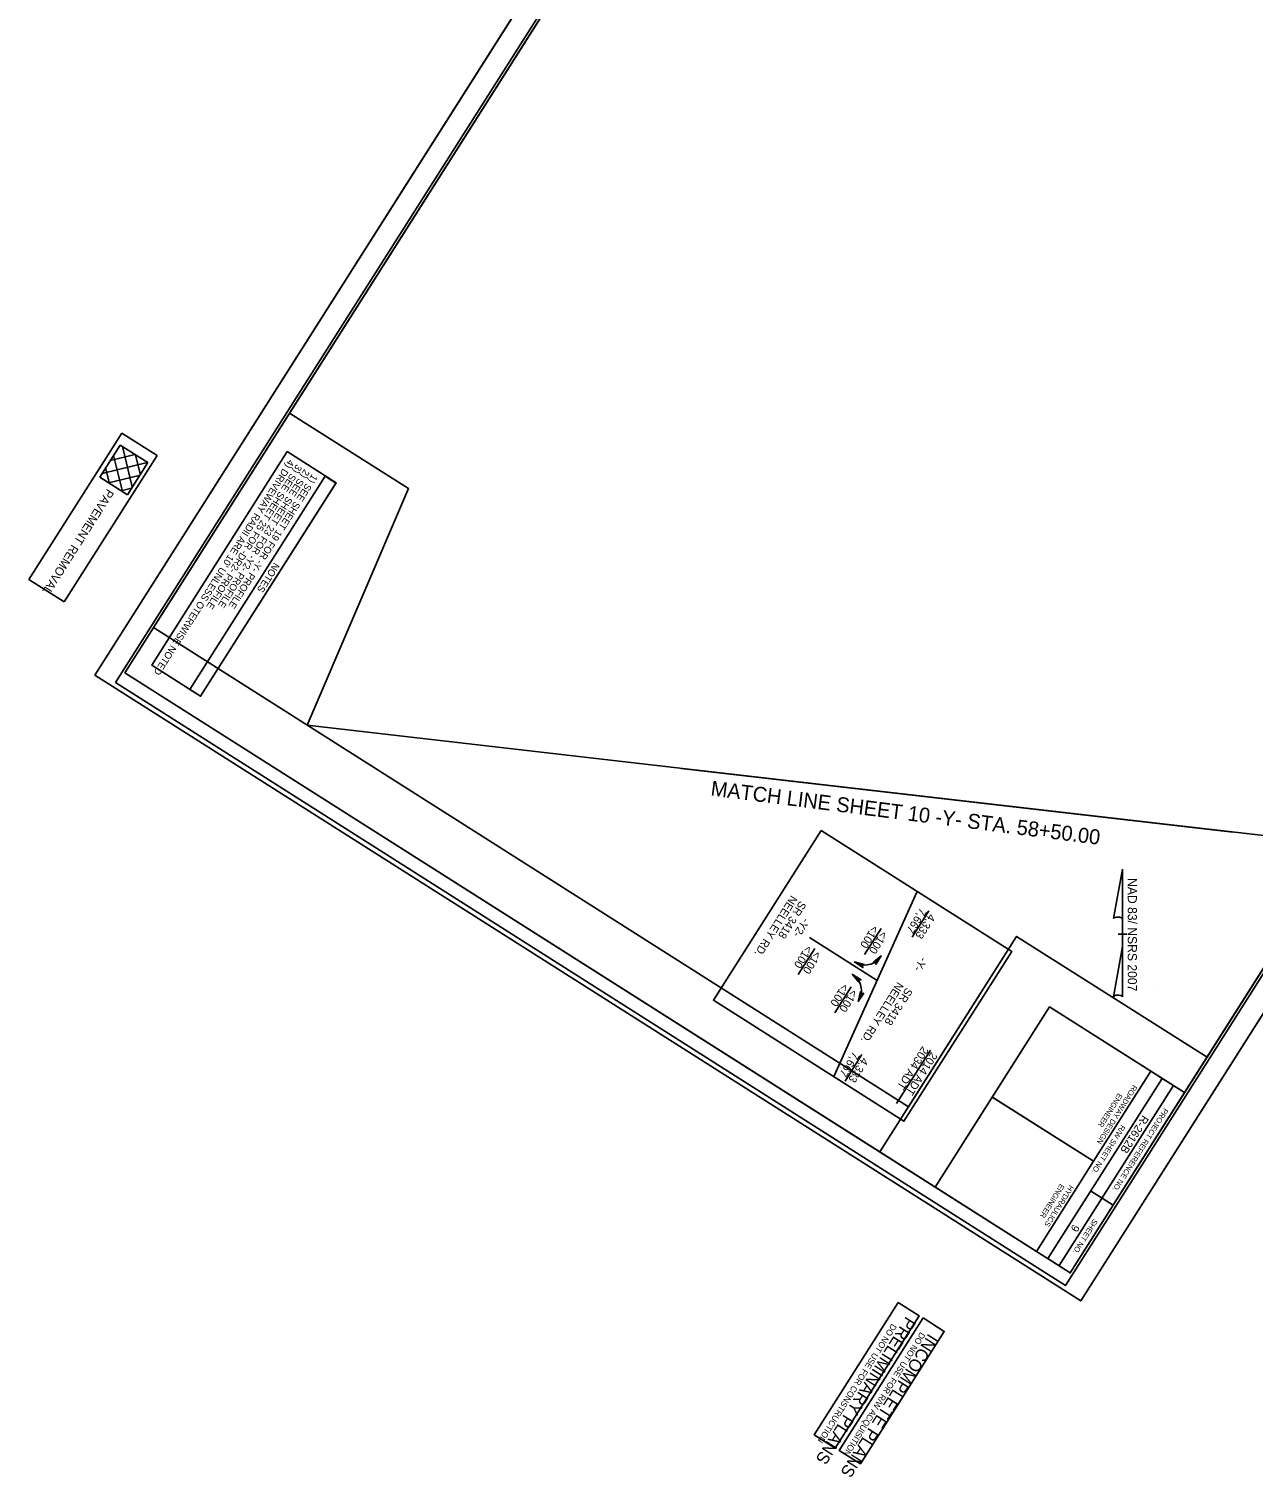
# Model space of a CAD drawing. Extents: x 1780138 to 1782093, y 811157 to 813450.
# Drawn here: x 1780138 to 1781286, y 811157 to 812514 of the extents above; entities that cross this region are included whole.
import ezdxf

# ---------------------------------------------------------------- set-up
doc = ezdxf.new("R2010")
doc.units = 0
for name, color, linetype in [('Prop Easement Aerial Utility', 7, 'Continuous'), ('Prop Easement Construction Station Offsets', 7, 'Continuous'), ('Prop Easement Danger Tree Area', 7, 'Continuous'), ('Prop Easement Danger Tree Area Text', 7, 'Continuous'), ('Prop Easement Permanent Drainage', 7, 'Continuous'), ('Prop Easement Permanent Drainage Station Offsets', 7, 'Continuous'), ('Prop Easement Permanent Drainage Utility', 7, 'Continuous'), ('Prop Easement Permanent Drainage Utility Station Offsets', 7, 'Continuous'), ('Prop Easement Permanent Utility', 7, 'Continuous'), ('Prop Easement Permanent Utility Station Offsets', 7, 'Continuous'), ('Prop Easement Temporary Drainage', 7, 'Continuous'), ('Prop Easement Temporary Drainage Station Offsets', 7, 'Continuous'), ('Prop Easement Temporary Utility', 7, 'Continuous'), ('Prop Easement Temporary Utility Station Offsets', 7, 'Continuous'), ('Prop Parcel Number CELL', 7, 'Continuous'), ('Prop ROW CA Lines', 7, 'Continuous'), ('Prop ROW Marker CELL', 7, 'Continuous'), ('Prop ROW Station Offsets', 7, 'Continuous')]:
    doc.layers.add(name, color=color, linetype=linetype)

msp = doc.modelspace()

# ---------------------------------------------------------------- linework, layer by layer
at = {"layer": 'Prop Easement Aerial Utility'}
for p, q in [((1781101.7, 813330), (1780199.6, 811908.6)), ((1781124.1, 811321.9), (1782026.2, 812743.3))]:
    msp.add_line(p, q, dxfattribs=at)
at = {"layer": 'Prop Easement Danger Tree Area'}
msp.add_lwpolyline([(1780976.3, 811306), (1780996.1, 811293.4), (1780917.4, 811169.3), (1780897.5, 811181.8)], close=True, dxfattribs=at)
at = {"layer": 'Prop Easement Danger Tree Area Text'}
for p, q in [((1780204.1, 812094.1), (1780223.2, 812124.2)), ((1780237, 812115.5), (1780214.1, 812109.9)), ((1780223.2, 812124.2), (1780249.1, 812107.8)), ((1780225.3, 812122.9), (1780234.6, 812085.1)), ((1780237.5, 812115.2), (1780241.9, 812097.2)), ((1780248.4, 812108), (1780206.3, 812097.7)), ((1780209.6, 812102.8), (1780213.2, 812088.4)), ((1780217, 812114.5), (1780225.4, 812080.6)), ((1780249.1, 812107.8), (1780230, 812077.7)), ((1780230, 812077.7), (1780204.1, 812094.1)), ((1780241.1, 812095.9), (1780212.4, 812088.9)), ((1780233.9, 812083.8), (1780224.1, 812081.4))]:
    msp.add_line(p, q, dxfattribs=at)
at = {"layer": 'Prop Easement Permanent Drainage'}
msp.add_lwpolyline([(1780952.8, 811320.5), (1780972.6, 811307.9), (1780893.9, 811183.8), (1780874, 811196.4)], close=True, dxfattribs=at)
at = {"layer": 'Prop Easement Permanent Drainage Utility'}
msp.add_line((1781196.3, 811613.7), (1781196.3, 811613.7), dxfattribs=at)
at = {"layer": 'Prop Easement Permanent Drainage Utility Station Offsets'}
for p, q in [((1780224.8, 812135.5), (1780137.7, 811998.3)), ((1780258, 812114.5), (1780224.8, 812135.5)), ((1780170.8, 811977.2), (1780258, 812114.5)), ((1780137.7, 811998.3), (1780170.8, 811977.2))]:
    msp.add_line(p, q, dxfattribs=at)
for points in [[(1780379.8, 812118.1), (1780252.8, 811918), (1780298.7, 811888.8), (1780425.7, 812088.9)], [(1780415.5, 812095.1), (1780288.6, 811895.2), (1780298.7, 811888.8), (1780425.6, 812088.7)]]:
    msp.add_lwpolyline(points, close=True, dxfattribs=at)
at = {"layer": 'Prop Easement Permanent Utility'}
msp.add_lwpolyline([(1781004.7, 813135.2), (1780254.5, 811953.1), (1780962.5, 811503.8), (1781063.9, 811663.6), (1781242.5, 811550.3), (1781891.2, 812572.6)], close=True, dxfattribs=at)
at = {"layer": 'Prop Easement Permanent Utility Station Offsets'}
for p, q in [((1780892.7, 811533), (1780970.5, 811705.1)), ((1780981.6, 811687.5), (1780965.9, 811662.9)), ((1780936.9, 811671.1), (1780921.3, 811646.6)), ((1780869.6, 811662.6), (1780933.1, 811622.4)), ((1780874.8, 811652.4), (1780859.2, 811627.9)), ((1780908.9, 811616.5), (1780893.3, 811592)), ((1780918.8, 811552.8), (1780903.1, 811528.1)), ((1780983.1, 811556.9), (1780951.4, 811506.9))]:
    msp.add_line(p, q, dxfattribs=at)
for points in [[(1780880.7, 811763), (1781059.4, 811649.6), (1780958.3, 811490.4), (1780779.6, 811603.8)], [(1780921, 811637.4), (1780911.9, 811639.7), (1780919.8, 811634.5), (1780919.4, 811636.5)], [(1780932, 811637.3), (1780937, 811645.3), (1780929.6, 811639.4), (1780931.7, 811639.2)], [(1780915.9, 811620.7), (1780909.9, 811628), (1780918, 811623.1), (1780916, 811622.6)], [(1780920.5, 811610.6), (1780915.4, 811602.7), (1780917.6, 811611.9), (1780918.7, 811610.1)]]:
    msp.add_lwpolyline(points, close=True, dxfattribs=at)
for centre, start, end in [((1780921.6, 811655), 237.6535, 282.0054), ((1780921.6, 811655), 282.0054, 326.3572), ((1780900.2, 811612.6), 13.2994, 57.6513), ((1780900.2, 811612.6), 328.9475, 13.2994)]:
    msp.add_arc(centre, 18.2, start, end, dxfattribs=at)
at = {"layer": 'Prop Easement Temporary Drainage'}
for p, q in [((1781200.3, 811530.6), (1781189.7, 811537.3)), ((1781200.3, 811530.6), (1781093.1, 811361.7)), ((1781200.3, 811530.6), (1781093.1, 811361.7)), ((1781210.9, 811523.9), (1781103.7, 811355)), ((1781136.1, 811452.8), (1781041.2, 811513.1)), ((1781154.4, 811411.7), (1781133.3, 811425))]:
    msp.add_line(p, q, dxfattribs=at)
for points in [[(1781114.3, 811348.3), (1781918, 812614.8), (1781031.5, 813177.4), (1780227.7, 811910.9)], [(1781031.5, 813177.4), (1781918, 812614.8), (1781221.5, 811517.2), (1781094.8, 811597.6), (1780987.6, 811428.7), (1780227.7, 811910.9)], [(1781189.7, 811537.3), (1781136.1, 811452.8), (1781041.1, 811513.1), (1781094.8, 811597.6)], [(1781221.5, 811517.2), (1781114.3, 811348.3), (1781093.1, 811361.7), (1781200.3, 811530.6)], [(1781136.1, 811452.8), (1781082.6, 811368.4), (1780987.6, 811428.7), (1781041.1, 811513.1)]]:
    msp.add_lwpolyline(points, close=True, dxfattribs=at)
at = {"layer": 'Prop Easement Temporary Drainage Station Offsets'}
for p, q in [((1781154.9, 811680.4), (1781163.1, 811726.7)), ((1781163.1, 811726.7), (1781163.1, 811726.7)), ((1781163.1, 811726.7), (1781163.1, 811726.7)), ((1781163.1, 811726.7), (1781163.1, 811678.9)), ((1781163.1, 811654.1), (1781163.1, 811680.3)), ((1781163.1, 811678.9), (1781163.1, 811680.3)), ((1781163.1, 811654.1), (1781154.8, 811606.9)), ((1781162.7, 811665.7), (1781159.1, 811665.7)), ((1781159.1, 811665.7), (1781159.1, 811665.7)), ((1781159.2, 811665.7), (1781167.2, 811665.7)), ((1781163.2, 811607.1), (1781163.1, 811654.1))]:
    msp.add_line(p, q, dxfattribs=at)
for centre, start_param, end_param in [((1781159, 811679.9), 0.216388, 2.908219), ((1781159, 811606.7), 0.201328, 3.141593)]:
    msp.add_ellipse(centre, major_axis=(4.23, -0.03), ratio=0.461098, start_param=start_param, end_param=end_param, dxfattribs=at)
at = {"layer": 'Prop Easement Temporary Utility'}
for points in [[(1781918, 812614.8), (1781031.5, 813177.4), (1780227.7, 811910.9), (1780935.7, 811461.6), (1781063.9, 811663.6), (1781242.5, 811550.3)], [(1781063.9, 811663.6), (1780935.7, 811461.6), (1781114.2, 811348.2), (1781242.5, 811550.3)]]:
    msp.add_lwpolyline(points, close=True, dxfattribs=at)
at = {"layer": 'Prop Easement Temporary Utility Station Offsets'}
msp.add_line((1780749.2, 811821.2), (1781266.8, 811761.5), dxfattribs=at)
at = {"layer": 'Prop ROW CA Lines'}
msp.add_lwpolyline([(1781101.7, 813330), (1780199.6, 811908.6), (1781124.1, 811321.9), (1782026.2, 812743.3)], close=True, dxfattribs=at)
at = {"layer": 'Prop ROW Marker CELL'}
msp.add_lwpolyline([(1781516.2, 811981.6), (1781369.5, 812074.6), (1781637.4, 812498.2), (1781665.8, 812542.9), (1781507.5, 812669.1), (1780938.2, 813030.4), (1780382.1, 812154.2), (1780493.5, 812083.5), (1780398.6, 811861.6), (1781369, 811749.7)], close=True, dxfattribs=at)
at = {"layer": 'Prop ROW Station Offsets'}
msp.add_lwpolyline([(1781111.6, 813308.3), (1780218.9, 811901.7), (1781109.7, 811336.4), (1782002.3, 812743)], close=True, dxfattribs=at)

# ---------------------------------------------------------------- texts
at = {"layer": 'Prop Easement Construction Station Offsets'}
msp.add_text('MATCH LINE SHEET 10 -Y- STA. 58+50.00', height=14, rotation=352.7698, dxfattribs=at).set_placement((1780776.5, 811795.8))
at = {"layer": 'Prop Easement Danger Tree Area'}
for s, height, p in [('INCOMPLETE PLANS', 11.52, (1780981.4, 811292.1)), ('DO NOT USE FOR R/W ACQUISITION', 5.76, (1780973.8, 811293.1))]:
    msp.add_text(s, height=height, rotation=237.6004, dxfattribs=at).set_placement(p)
at = {"layer": 'Prop Easement Permanent Drainage'}
for s, height, p in [('PRELIMINARY PLANS', 11.52, (1780960.4, 811308)), ('DO NOT USE FOR CONSTRUCTION', 5.76, (1780946.9, 811301))]:
    msp.add_text(s, height=height, rotation=237.6004, dxfattribs=at).set_placement(p)
at = {"layer": 'Prop Easement Permanent Drainage Station Offsets'}
for s, height, rotation, p in [("4) DRIVEWAY RADII ARE 10' UNLESS OTERWISE NOTED", 6.56, 237.6004, (1780381.4, 812111.4)), ('3) SEE SHEET 25 FOR -DR2- PROFILE', 6.56, 237.6004, (1780388.7, 812106.8)), ('2) SEE SHEET 23 FOR -Y2- PROFILE', 6.56, 237.6004, (1780395.9, 812102.2)), ('1) SEE SHEET 19 FOR -Y- PROFILE ', 6.56, 237.6004, (1780403.2, 812097.6)), ('PAVEMENT REMOVAL', 8, 237.5792, (1780211.1, 812083.8)), ('NOTES', 6.64, 237.6004, (1780367.6, 812014.6))]:
    msp.add_text(s, height=height, rotation=rotation, dxfattribs=at).set_placement(p)
at = {"layer": 'Prop Easement Permanent Utility Station Offsets'}
for s, rotation, p in [('NEELLEY RD.', 237.6525, (1780852.5, 811702.7)), ('SR 3418', 237.6525, (1780860.8, 811697.5)), ('7,667', 237.6006, (1780973.7, 811690.8)), ('4,333', 237.6006, (1780982, 811685.6)), ('-Y2-', 237.4321, (1780864.1, 811681.7)), ('<100', 237.6006, (1780928.9, 811674.7)), ('<100', 237.6006, (1780937.2, 811669.4)), ('<100', 237.6006, (1780866.8, 811655.9)), ('<100', 237.6006, (1780875.1, 811650.6)), ('-Y-', 238.1263, (1780974.2, 811645)), ('<100', 237.6006, (1780900.9, 811620.1)), ('<100', 237.6006, (1780909.2, 811614.8)), ('NEELLEY RD.', 237.6525, (1780952.2, 811621.5)), ('SR 3418', 237.6525, (1780960.5, 811616.3)), (' 2034 ADT', 237.6006, (1780977.1, 811563.5)), ('7,667', 237.6006, (1780910.9, 811556.1)), ('4,333', 237.6006, (1780919.2, 811550.8)), (' 2014 ADT', 237.6006, (1780985.4, 811558.2))]:
    msp.add_text(s, height=7.5, rotation=rotation, dxfattribs=at).set_placement(p)
at = {"layer": 'Prop Easement Temporary Drainage'}
for s, p in [('ROADWAY DESIGN', (1781173.2, 811524.9)), ('ENGINEER', (1781159.3, 811517.1)), ('PROJECT REFERENCE NO.', (1781202.2, 811503.1)), ('R/W SHEET NO.', (1781162, 811487.4)), ('ENGINEER', (1781104.9, 811432.1)), ('HYDRAULICS', (1781113.7, 811431)), ('SHEET NO.', (1781136.1, 811399.2))]:
    msp.add_text(s, height=5, rotation=237.6004, dxfattribs=at).set_placement(p)
at = {"layer": 'Prop Easement Temporary Drainage Station Offsets'}
msp.add_text('NAD 83/ NSRS 2007', height=8.5, rotation=270, dxfattribs=at).set_placement((1781168.2, 811718.3))
at = {"layer": 'Prop Parcel Number CELL'}
for s, p in [('R-2612B  ', (1781182, 811496.7)), ('9', (1781117.2, 811394.4))]:
    msp.add_text(s, height=7.5, rotation=237.6004, dxfattribs=at).set_placement(p)

doc.saveas('drawing.dxf')
